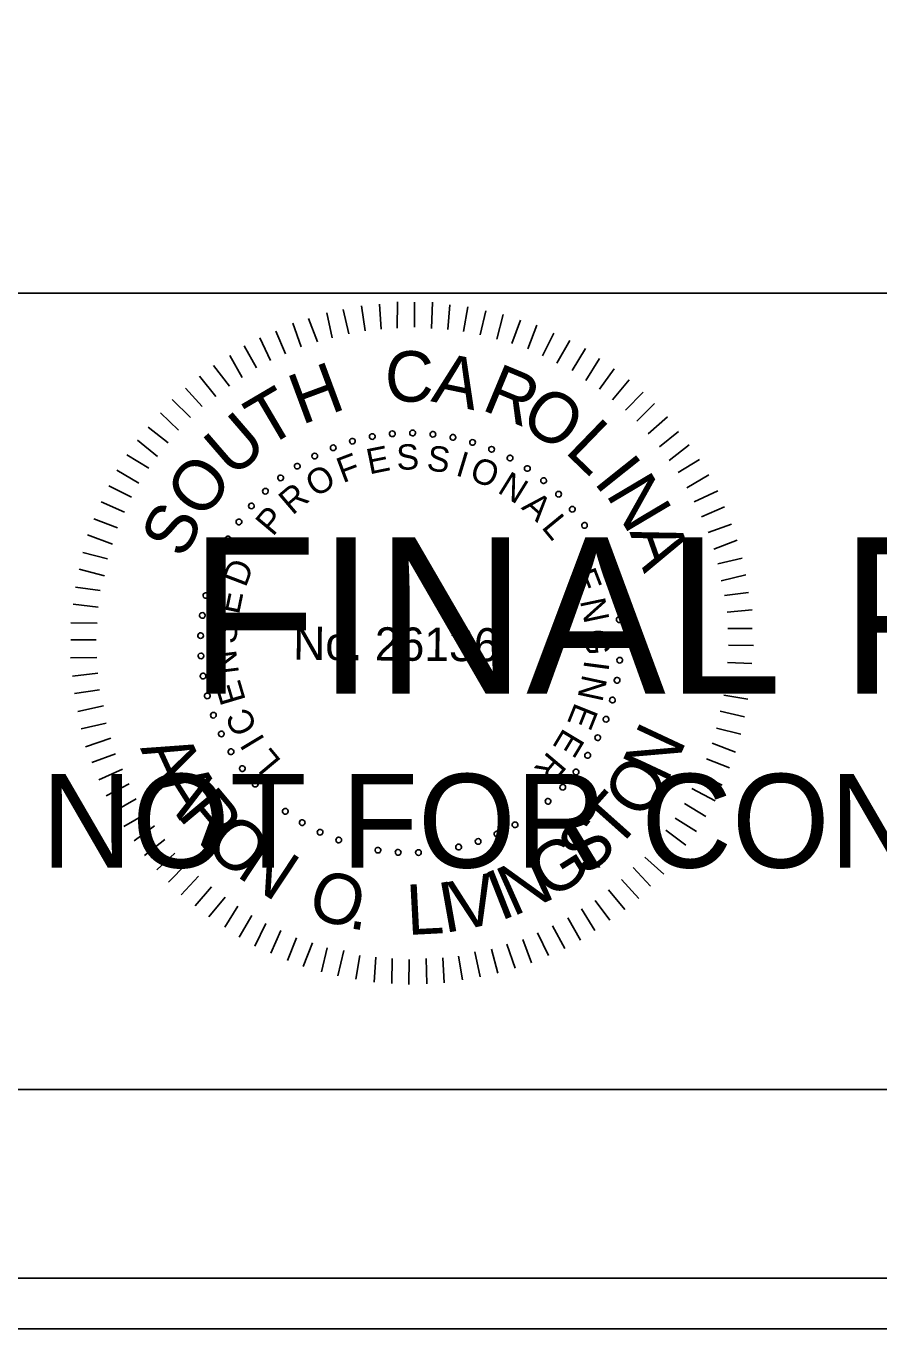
# Model space of a CAD drawing. Extents: x 967 to 1623, y 964 to 7064.
# Drawn here: x 1170.56 to 1189.3, y 5163.72 to 5192.36 of the extents above; entities that cross this region are included whole.
import ezdxf

# ---------------------------------------------------------------- set-up
doc = ezdxf.new("R2010")
doc.units = 0
for name, color, linetype in [('RD_SHT_Bndy', 7, 'Continuous'), ('RD_SHT_IplotShp', 7, 'Continuous'), ('RD_SHT_Misc1', 7, 'Continuous'), ('RD_SHT_Misc2', 7, 'Continuous'), ('RD_Sketch1', 7, 'Continuous')]:
    doc.layers.add(name, color=color, linetype=linetype)

msp = doc.modelspace()

# ---------------------------------------------------------------- linework, layer by layer
at = {"layer": 'RD_SHT_Bndy'}
for p, q in [((996.114, 5186.486), (1323.886, 5186.486)), ((1323.886, 5168.983), (996.114, 5168.983))]:
    msp.add_line(p, q, dxfattribs=at)
at = {"layer": 'RD_SHT_IplotShp'}
for points in [[(967.409, 5163.72), (1326.285, 5163.72), (1326.285, 5383.72), (967.409, 5383.72)], [(988.525, 5164.84), (1326.285, 5164.84), (1326.285, 5382.6), (988.525, 5382.6)]]:
    msp.add_lwpolyline(points, close=True, dxfattribs=at)
at = {"layer": 'RD_SHT_Misc1'}
for p, q in [((1177.657, 5185.597), (1177.53, 5186.128)), ((1178.01, 5185.663), (1177.93, 5186.209)), ((1178.364, 5185.699), (1178.33, 5186.244)), ((1178.717, 5185.719), (1178.722, 5186.295)), ((1179.093, 5185.739), (1179.098, 5186.292)), ((1179.469, 5185.713), (1179.489, 5186.288)), ((1179.829, 5185.687), (1179.872, 5186.231)), ((1180.174, 5185.646), (1180.271, 5186.19)), ((1180.535, 5185.573), (1180.662, 5186.102)), ((1176.61, 5185.306), (1176.423, 5185.83)), ((1176.964, 5185.419), (1176.769, 5185.935)), ((1177.287, 5185.508), (1177.169, 5186.054)), ((1180.902, 5185.478), (1181.045, 5186.022)), ((1181.231, 5185.384), (1181.428, 5185.896)), ((1176.264, 5185.156), (1176.053, 5185.657)), ((1181.584, 5185.265), (1181.78, 5185.786)), ((1181.905, 5185.109), (1182.154, 5185.606)), ((1175.624, 5184.846), (1175.352, 5185.332)), ((1175.933, 5185.005), (1175.699, 5185.506)), ((1182.226, 5184.953), (1182.506, 5185.45)), ((1182.562, 5184.789), (1182.85, 5185.27)), ((1175.308, 5184.634), (1175.036, 5185.12)), ((1182.86, 5184.572), (1183.163, 5185.053)), ((1174.729, 5184.217), (1174.372, 5184.665)), ((1175.03, 5184.445), (1174.681, 5184.9)), ((1183.158, 5184.378), (1183.484, 5184.828)), ((1174.435, 5183.997), (1174.062, 5184.399)), ((1183.447, 5184.145), (1183.811, 5184.587)), ((1174.172, 5183.753), (1173.776, 5184.148)), ((1183.729, 5183.92), (1184.116, 5184.316)), ((1173.909, 5183.479), (1173.52, 5183.858)), ((1183.98, 5183.672), (1184.368, 5184.061)), ((1173.684, 5183.197), (1173.242, 5183.546)), ((1184.232, 5183.394), (1184.657, 5183.767)), ((1173.451, 5182.9), (1173.009, 5183.256)), ((1184.475, 5183.108), (1184.892, 5183.45)), ((1184.687, 5182.807), (1185.128, 5183.156)), ((1173.257, 5182.64), (1172.776, 5182.936)), ((1184.885, 5182.544), (1185.355, 5182.832)), ((1173.039, 5182.312), (1172.559, 5182.6)), ((1185.081, 5182.213), (1185.56, 5182.493)), ((1172.883, 5182.006), (1172.379, 5182.256)), ((1185.24, 5181.904), (1185.756, 5182.145)), ((1172.727, 5181.677), (1172.215, 5181.904)), ((1172.571, 5181.333), (1172.051, 5181.53)), ((1185.399, 5181.573), (1185.907, 5181.791)), ((1185.549, 5181.226), (1186.057, 5181.414)), ((1172.461, 5180.974), (1171.91, 5181.178)), ((1185.669, 5180.865), (1186.185, 5181.06)), ((1172.351, 5180.652), (1171.807, 5180.787)), ((1185.759, 5180.541), (1186.297, 5180.667)), ((1172.286, 5180.276), (1171.727, 5180.419)), ((1185.832, 5180.165), (1186.371, 5180.298)), ((1172.191, 5179.955), (1171.647, 5180.029)), ((1185.906, 5179.842), (1186.436, 5179.906)), ((1172.15, 5179.587), (1171.598, 5179.653)), ((1185.964, 5179.473), (1186.51, 5179.53)), ((1172.124, 5179.234), (1171.548, 5179.239)), ((1185.977, 5179.12), (1186.514, 5179.115)), ((1172.105, 5178.866), (1171.545, 5178.871)), ((1185.997, 5178.751), (1186.542, 5178.747)), ((1172.118, 5178.482), (1171.542, 5178.471)), ((1185.971, 5178.368), (1186.508, 5178.348)), ((1172.138, 5178.136), (1171.585, 5178.072)), ((1185.952, 5178.022), (1186.497, 5177.949)), ((1172.173, 5177.768), (1171.627, 5177.688)), ((1185.888, 5177.655), (1186.417, 5177.566)), ((1172.262, 5177.414), (1171.701, 5177.296)), ((1185.808, 5177.302), (1186.345, 5177.175)), ((1172.321, 5177.037), (1171.774, 5176.911)), ((1185.729, 5176.926), (1186.265, 5176.792)), ((1172.425, 5176.707), (1171.871, 5176.519)), ((1172.53, 5176.36), (1172.007, 5176.173)), ((1185.634, 5176.597), (1186.146, 5176.401)), ((1185.508, 5176.253), (1186.013, 5176.057)), ((1172.681, 5176.029), (1172.165, 5175.788)), ((1185.352, 5175.924), (1185.857, 5175.675)), ((1172.831, 5175.705), (1172.323, 5175.441)), ((1185.188, 5175.603), (1185.7, 5175.33)), ((1172.982, 5175.374), (1172.497, 5175.094)), ((1185.024, 5175.274), (1185.498, 5174.987)), ((1173.194, 5175.042), (1172.709, 5174.762)), ((1184.822, 5174.946), (1185.288, 5174.658)), ((1173.384, 5174.78), (1172.936, 5174.453)), ((1184.62, 5174.687), (1185.055, 5174.353)), ((1173.612, 5174.478), (1173.164, 5174.129)), ((1184.403, 5174.389), (1184.814, 5174.033)), ((1173.832, 5174.177), (1173.437, 5173.812)), ((1184.155, 5174.092), (1184.574, 5173.72)), ((1174.091, 5173.945), (1173.689, 5173.541)), ((1183.899, 5173.864), (1184.28, 5173.454)), ((1174.35, 5173.674), (1173.97, 5173.263)), ((1183.644, 5173.597), (1184.024, 5173.18)), ((1174.64, 5173.442), (1174.275, 5173.022)), ((1174.937, 5173.209), (1174.58, 5172.782)), ((1183.358, 5173.37), (1183.715, 5172.944)), ((1175.212, 5173.014), (1174.932, 5172.549)), ((1182.764, 5172.952), (1183.059, 5172.482)), ((1183.065, 5173.141), (1183.384, 5172.709)), ((1175.525, 5172.812), (1175.245, 5172.331)), ((1175.83, 5172.633), (1175.588, 5172.136)), ((1182.463, 5172.755), (1182.743, 5172.269)), ((1176.159, 5172.477), (1175.94, 5171.98)), ((1181.8, 5172.431), (1182.041, 5171.93)), ((1182.124, 5172.581), (1182.396, 5172.08)), ((1176.503, 5172.321), (1176.307, 5171.816)), ((1176.855, 5172.211), (1176.651, 5171.69)), ((1177.177, 5172.1), (1177.05, 5171.572)), ((1180.791, 5172.07), (1180.926, 5171.54)), ((1181.122, 5172.175), (1181.31, 5171.652)), ((1181.476, 5172.28), (1181.664, 5171.771)), ((1177.545, 5172.036), (1177.409, 5171.484)), ((1177.897, 5171.933), (1177.808, 5171.412)), ((1178.25, 5171.892), (1178.207, 5171.34)), ((1178.603, 5171.866), (1178.598, 5171.313)), ((1178.978, 5171.84), (1178.974, 5171.295)), ((1179.355, 5171.86), (1179.365, 5171.307)), ((1179.715, 5171.88), (1179.749, 5171.327)), ((1180.061, 5171.915), (1180.149, 5171.393)), ((1180.423, 5172.012), (1180.541, 5171.458))]:
    msp.add_line(p, q, dxfattribs=at)
for centre, start, end in [((1177.734, 5183.235), 16.1422, 196.1422), ((1177.734, 5183.235), 196.1422, 16.1422), ((1178.168, 5183.337), 10.6038, 190.6038), ((1178.168, 5183.337), 190.6038, 10.6038), ((1178.609, 5183.397), 5.0653, 185.0653), ((1178.609, 5183.397), 185.0653, 5.0653), ((1179.055, 5183.414), 359.5268, 179.5268), ((1179.055, 5183.414), 179.5268, 359.5268), ((1179.5, 5183.388), 353.9884, 173.9884), ((1179.5, 5183.388), 173.9884, 353.9884), ((1179.94, 5183.319), 168.4499, 348.4499), ((1179.94, 5183.319), 348.4499, 168.4499), ((1180.372, 5183.208), 162.9114, 342.9114), ((1180.372, 5183.208), 342.9114, 162.9114), ((1176.906, 5182.908), 27.2191, 207.2191), ((1177.312, 5183.091), 21.6807, 201.6807), ((1177.312, 5183.091), 201.6807, 21.6807), ((1180.79, 5183.056), 157.373, 337.373), ((1180.79, 5183.056), 337.373, 157.373), ((1176.52, 5182.686), 32.7576, 212.7576), ((1176.52, 5182.686), 212.7576, 32.7576), ((1176.906, 5182.908), 207.2191, 27.2191), ((1181.193, 5182.864), 151.8345, 331.8345), ((1181.193, 5182.864), 331.8345, 151.8345), ((1181.574, 5182.634), 146.2961, 326.2961), ((1181.574, 5182.634), 326.2961, 146.2961), ((1176.156, 5182.428), 38.2961, 218.2961), ((1176.156, 5182.428), 218.2961, 38.2961), ((1181.932, 5182.368), 140.7576, 320.7576), ((1181.932, 5182.368), 320.7576, 140.7576), ((1175.82, 5182.135), 43.8345, 223.8345), ((1175.82, 5182.135), 223.8345, 43.8345), ((1182.263, 5182.069), 135.2191, 315.2191), ((1182.263, 5182.069), 315.2191, 135.2191), ((1175.513, 5181.812), 49.373, 229.373), ((1175.513, 5181.812), 229.373, 49.373), ((1182.563, 5181.74), 309.6807, 129.6807), ((1175.239, 5181.461), 54.9114, 234.9114), ((1175.239, 5181.461), 234.9114, 54.9114), ((1182.563, 5181.74), 129.6807, 309.6807), ((1182.83, 5181.383), 124.1422, 304.1422), ((1182.83, 5181.383), 304.1422, 124.1422), ((1175, 5181.085), 60.4499, 240.4499), ((1175, 5181.085), 240.4499, 60.4499), ((1183.061, 5181.002), 118.6038, 298.6038), ((1183.061, 5181.002), 298.6038, 118.6038), ((1174.798, 5180.687), 65.9884, 245.9884), ((1174.798, 5180.687), 245.9884, 65.9884), ((1183.255, 5180.601), 113.0653, 293.0653), ((1183.255, 5180.601), 293.0653, 113.0653), ((1174.636, 5180.272), 71.5268, 251.5268), ((1174.636, 5180.272), 251.5268, 71.5268), ((1183.408, 5180.182), 107.5268, 287.5268), ((1183.408, 5180.182), 287.5268, 107.5268), ((1174.514, 5179.843), 77.0653, 257.0653), ((1174.514, 5179.843), 257.0653, 77.0653), ((1183.521, 5179.751), 101.9884, 281.9884), ((1183.521, 5179.751), 281.9884, 101.9884), ((1174.435, 5179.405), 82.6038, 262.6038), ((1174.435, 5179.405), 262.6038, 82.6038), ((1183.592, 5179.311), 96.4499, 276.4499), ((1183.592, 5179.311), 276.4499, 96.4499), ((1174.398, 5178.961), 88.1422, 268.1422), ((1174.398, 5178.961), 268.1422, 88.1422), ((1183.619, 5178.866), 90.9114, 270.9114), ((1183.619, 5178.866), 270.9114, 90.9114), ((1174.404, 5178.515), 93.6807, 273.6807), ((1174.404, 5178.515), 273.6807, 93.6807), ((1183.604, 5178.421), 85.373, 265.373), ((1183.604, 5178.421), 265.373, 85.373), ((1174.453, 5178.072), 99.2191, 279.2191), ((1174.453, 5178.072), 279.2191, 99.2191), ((1183.546, 5177.979), 79.8345, 259.8345), ((1183.546, 5177.979), 259.8345, 79.8345), ((1174.545, 5177.636), 104.7576, 284.7576), ((1174.545, 5177.636), 284.7576, 104.7576), ((1183.445, 5177.545), 74.2961, 254.2961), ((1183.445, 5177.545), 254.2961, 74.2961), ((1174.678, 5177.211), 110.2961, 290.2961), ((1174.678, 5177.211), 290.2961, 110.2961), ((1183.303, 5177.122), 68.7576, 248.7576), ((1183.303, 5177.122), 248.7576, 68.7576), ((1174.852, 5176.8), 115.8345, 295.8345), ((1174.852, 5176.8), 295.8345, 115.8345), ((1183.121, 5176.716), 63.2191, 243.2191), ((1183.121, 5176.716), 243.2191, 63.2191), ((1175.065, 5176.409), 121.373, 301.373), ((1175.065, 5176.409), 301.373, 121.373), ((1182.9, 5176.328), 57.6807, 237.6807), ((1182.9, 5176.328), 237.6807, 57.6807), ((1175.314, 5176.039), 126.9114, 306.9114), ((1175.314, 5176.039), 306.9114, 126.9114), ((1182.643, 5175.964), 52.1422, 232.1422), ((1182.643, 5175.964), 232.1422, 52.1422), ((1175.598, 5175.696), 132.4499, 312.4499), ((1175.598, 5175.696), 312.4499, 132.4499), ((1182.353, 5175.627), 46.6038, 226.6038), ((1182.353, 5175.627), 226.6038, 46.6038), ((1175.914, 5175.381), 137.9884, 317.9884), ((1175.914, 5175.381), 317.9884, 137.9884), ((1182.03, 5175.319), 41.0653, 221.0653), ((1182.03, 5175.319), 221.0653, 41.0653), ((1176.258, 5175.099), 143.5268, 323.5268), ((1176.258, 5175.099), 323.5268, 143.5268), ((1181.68, 5175.043), 35.5268, 215.5268), ((1181.68, 5175.043), 215.5268, 35.5268), ((1176.629, 5174.851), 149.0653, 329.0653), ((1176.629, 5174.851), 329.0653, 149.0653), ((1177.021, 5174.639), 154.6038, 334.6038), ((1177.021, 5174.639), 334.6038, 154.6038), ((1180.908, 5174.6), 24.4499, 204.4499), ((1181.305, 5174.803), 29.9884, 209.9884), ((1181.305, 5174.803), 209.9884, 29.9884), ((1177.432, 5174.467), 160.1422, 340.1422), ((1177.432, 5174.467), 340.1422, 160.1422), ((1177.858, 5174.335), 165.6807, 345.6807), ((1177.858, 5174.335), 345.6807, 165.6807), ((1180.065, 5174.313), 13.373, 193.373), ((1180.494, 5174.436), 18.9114, 198.9114), ((1180.494, 5174.436), 198.9114, 18.9114), ((1180.908, 5174.6), 204.4499, 24.4499), ((1178.294, 5174.245), 351.2191, 171.2191), ((1178.294, 5174.245), 171.2191, 351.2191), ((1178.737, 5174.198), 356.7576, 176.7576), ((1178.737, 5174.198), 176.7576, 356.7576), ((1179.183, 5174.193), 2.2961, 182.2961), ((1179.183, 5174.193), 182.2961, 2.2961), ((1179.627, 5174.232), 7.8345, 187.8345), ((1179.627, 5174.232), 187.8345, 7.8345), ((1180.065, 5174.313), 193.373, 13.373)]:
    msp.add_arc(centre, 0.0627, start, end, dxfattribs=at)
at = {"layer": 'RD_Sketch1'}
msp.add_lwpolyline([(967.409, 5163.72), (1326.285, 5163.72), (1326.285, 5383.72), (967.409, 5383.72)], close=True, dxfattribs=at)

# ---------------------------------------------------------------- texts
at = {"layer": 'RD_SHT_Misc1'}
for s, height, rotation, p in [('C', 1.11, 359.5482, (1178.442, 5184.108)), ('H', 1.11, 20.3637, (1176.614, 5183.587)), ('A', 1.11, 348.1981, (1179.439, 5184.115)), ('R', 1.11, 337.4344, (1180.541, 5183.937)), ('T', 1.11, 30.4992, (1175.828, 5183.072)), ('O', 1.108, 326.5869, (1181.366, 5183.609)), ('U', 1.11, 40.8022, (1175.102, 5182.403)), ('L', 1.11, 315.9488, (1182.373, 5183.003)), ('F', 0.557, 20.6127, (1177.52, 5182.309)), ('E', 0.557, 11.4103, (1178.103, 5182.503)), ('S', 0.557, 2.208, (1178.709, 5182.601)), ('S', 0.557, 352.6608, (1179.346, 5182.599)), ('I', 0.557, 343.1136, (1179.975, 5182.491)), ('O', 1.11, 52.0267, (1174.435, 5181.474)), ('O', 0.557, 30.8477, (1176.917, 5181.987)), ('O', 0.557, 338.4392, (1180.274, 5182.401)), ('I', 1.11, 308.6613, (1183.011, 5182.338)), ('N', 0.557, 328.2042, (1180.896, 5182.12)), ('N', 1.11, 300.7037, (1183.285, 5182.075)), ('R', 0.557, 40.3949, (1176.415, 5181.594)), ('S', 1.108, 63.2511, (1174.029, 5180.619)), ('A', 0.557, 318.657, (1181.424, 5181.762)), ('P', 0.557, 49.9421, (1175.985, 5181.124)), ('L', 0.557, 309.4546, (1181.869, 5181.339)), ('A', 1.11, 289.4792, (1183.814, 5181.243)), ('D', 0.557, 69.0364, (1175.386, 5180.003)), ('E', 0.557, 291.049, (1182.53, 5180.307)), ('E', 0.557, 78.2388, (1175.238, 5179.407)), ('N', 0.557, 281.8466, (1182.728, 5179.726)), ('S', 0.557, 87.786, (1175.187, 5178.772)), ('No. 26136', 0.7311, 359.5268, (1176.429, 5178.43)), ('G', 0.557, 272.2995, (1182.833, 5179.097)), ('N', 0.557, 97.3332, (1175.242, 5178.137)), ('I', 0.557, 262.4084, (1182.83, 5178.437)), ('E', 0.557, 106.5355, (1175.394, 5177.541)), ('N', 0.557, 257.7339, (1182.789, 5178.127)), ('C', 0.557, 116.4266, (1175.661, 5176.938)), ('E', 0.557, 248.1867, (1182.628, 5177.511)), ('N', 1.105, 64.8922, (1184.632, 5175.684)), ('I', 0.557, 121.1011, (1175.823, 5176.67)), ('E', 0.557, 238.9844, (1182.378, 5176.949)), ('A', 1.105, 294.7297, (1173.062, 5176.486)), ('L', 0.557, 129.9595, (1176.187, 5176.204)), ('R', 0.557, 229.782, (1182.041, 5176.435)), ('O', 1.105, 56.2059, (1184.102, 5174.874)), ('A', 1.105, 302.2892, (1173.414, 5175.72)), ('R', 1.105, 309.8487, (1173.865, 5175.007)), ('T', 1.105, 48.2685, (1183.515, 5174.211)), ('O', 1.105, 317.7861, (1174.434, 5174.33)), ('S', 1.105, 40.3311, (1182.842, 5173.636)), ('N', 1.105, 326.4725, (1175.158, 5173.686)), ('G', 1.105, 32.0198, (1182.059, 5173.14)), ('N', 1.105, 24.0824, (1181.252, 5172.776)), ('O', 1.105, 342.3472, (1176.697, 5172.82)), ('I', 1.105, 21.4605, (1180.976, 5172.681)), ('L', 1.105, 2.9677, (1178.943, 5172.379)), ('I', 1.105, 10.1523, (1179.743, 5172.418)), ('V', 1.105, 12.7741, (1180.033, 5172.457)), ('.', 1.105, 351.0336, (1177.623, 5172.536))]:
    msp.add_text(s, height=height, rotation=rotation, dxfattribs=at).set_placement(p)
at = {"layer": 'RD_SHT_Misc2'}
for s, height, p in [('FINAL PLANS', 3.4375, (1174.145, 5177.685)), ('NOT FOR CONSTRUCTION', 2.0625, (1170.901, 5173.86))]:
    msp.add_text(s, height=height, dxfattribs=at).set_placement(p)

doc.saveas('drawing.dxf')
